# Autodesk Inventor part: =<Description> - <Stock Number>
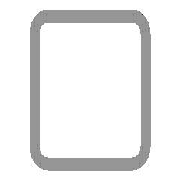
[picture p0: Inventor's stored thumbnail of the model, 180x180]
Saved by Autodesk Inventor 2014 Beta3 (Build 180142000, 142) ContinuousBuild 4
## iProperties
IsCustomPart: 1
_CCFamilyMember: 9
_CCFamilyDisplayName: ANSI AISC (Square) - Tube
_FrameMemberDoc: Frame Member File
_Version: 15.0.0
_GetPNFromCC: 1
Created: 2010-11
Part Number: =<Description> - <Stock Number>
Material: Steel, Mild
Description: Tube
Document SubType Name: Modeling
Standard: ANSI
Designer: Beta-8540w
Standards Organization: ANSI
Language: en-US
Size Designation: 3x3x3/16
Categories: <MemberInstance><Categories><Category DisplayName="Structural Shapes" InternalName="089c4875-fa83-4c05-b084-43b9cc11f5ed" Mnemonic="GRDR"><CategoryParameter Dis
Stock Number: 3x3x3/16
Density: 7.86 g/cm^3
Appearance: Steel
G_L: 16.000 in
G_W: 3.000 in
G_H: 3.000 in
Author: Beta-8540w
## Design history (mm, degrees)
node "Start plane"
node "End plane"
sketch "Sketch"
  geometry: L1 (-38.1, -28.575)-(-38.1, 28.575); L2 (-28.575, 38.1)-(28.575, 38.1); L3 (38.1, 28.575)-(38.1, -28.575); L4 (28.575, -38.1)-(-28.575, -38.1); L5 (-28.575, 33.337)-(28.575, 33.338); L6 (33.338, 28.575)-(33.338, -28.575); L7 (28.575, -33.337)-(-28.575, -33.338); L8 (-33.338, -28.575)-(-33.338, 28.575); L9 (0, 56.102)-(0, -56.102) reference; L10 (-56.102, 0)-(56.102, 0) reference; A1 r 9.525 centre (-28.575, -28.575) between (-38.1, -28.575) and (-28.575, -38.1); A2 r 9.525 centre (-28.575, 28.575) between (-28.575, 38.1) and (-38.1, 28.575); A3 r 9.525 centre (28.575, 28.575) between (38.1, 28.575) and (28.575, 38.1); A4 r 9.525 centre (28.575, -28.575) between (28.575, -38.1) and (38.1, -28.575); A5 r 4.763 centre (-28.575, 28.575) between (-28.575, 33.337) and (-33.338, 28.575); A6 r 4.763 centre (28.575, 28.575) between (33.338, 28.575) and (28.575, 33.338); A7 r 4.763 centre (28.575, -28.575) between (28.575, -33.337) and (33.338, -28.575); A8 r 4.763 centre (-28.575, -28.575) between (-33.338, -28.575) and (-28.575, -33.338)
  constraints: 16 end point, 16 point on circle, 8 centre point, 8 tangent, 4 parallel, 3 equal radius, 2 perpendicular, 7 other
  dimensions: "d10" = 76.2 distance between parallel lines of L2 L4 (= G_H); "d11" = 76.2 distance between parallel lines of L1 L3 (= G_W); "d12" = 4.7625 distance between parallel lines of L3 L6 (= G_T); "d15" = 38.1 distance between parallel lines of L2 L10 (= 0.5 x d10); "d16" = 38.1 distance between parallel lines of L9 L3 (= 0.5 x d11); "d17" = 9.525 radius of A1 (= G_IR)
extrude "Body" new body sketch "Sketch" stored distance "d3" = 406.4 (= G_L); taper "d4" = 0 deg
node "Driven Length"
  sketch "Sketch3"
    geometry: L1 (0, 0)-(10, 0) reference
    constraints: 2 end point, 1 horizontal
  workplane "Work Plane3"
  sketch "Sketch4"
    geometry: L1 (-2, -114.3)-(12, -114.3) reference; L2 (-2, 292.1)-(12, 292.1) reference
    dimensions: "d19" = 406.4 distance between parallel lines of L1 L2 (derived)
workplane "Work Plane4"
split "Split1"
body "Solid1"
other parameters: "G_W" = 76.2 [user parameter; used in 1 equation term], "G_H" = 76.2 [user parameter; used in 1 equation term], "G_T" = 4.7625 [user parameter; used in 1 equation term], "G_IR" = 9.525 [user parameter; used in 1 equation term], "G_L" = 406.4 (= d19) [user parameter; used in 1 equation term], "G_OFFSET_START" = 114.3 [user parameter; used in 1 equation term], "G_OFFSET_END" = 38.1 [user parameter; used in 1 equation term], "d13" = -114.3 (= -G_OFFSET_START), "d14" = 292.1 (= G_OFFSET_END + B_L), "B_L" = 254 [user parameter; used in 1 equation term], "d18" = 90 deg
